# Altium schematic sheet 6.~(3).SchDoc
size 420 x 297 mm
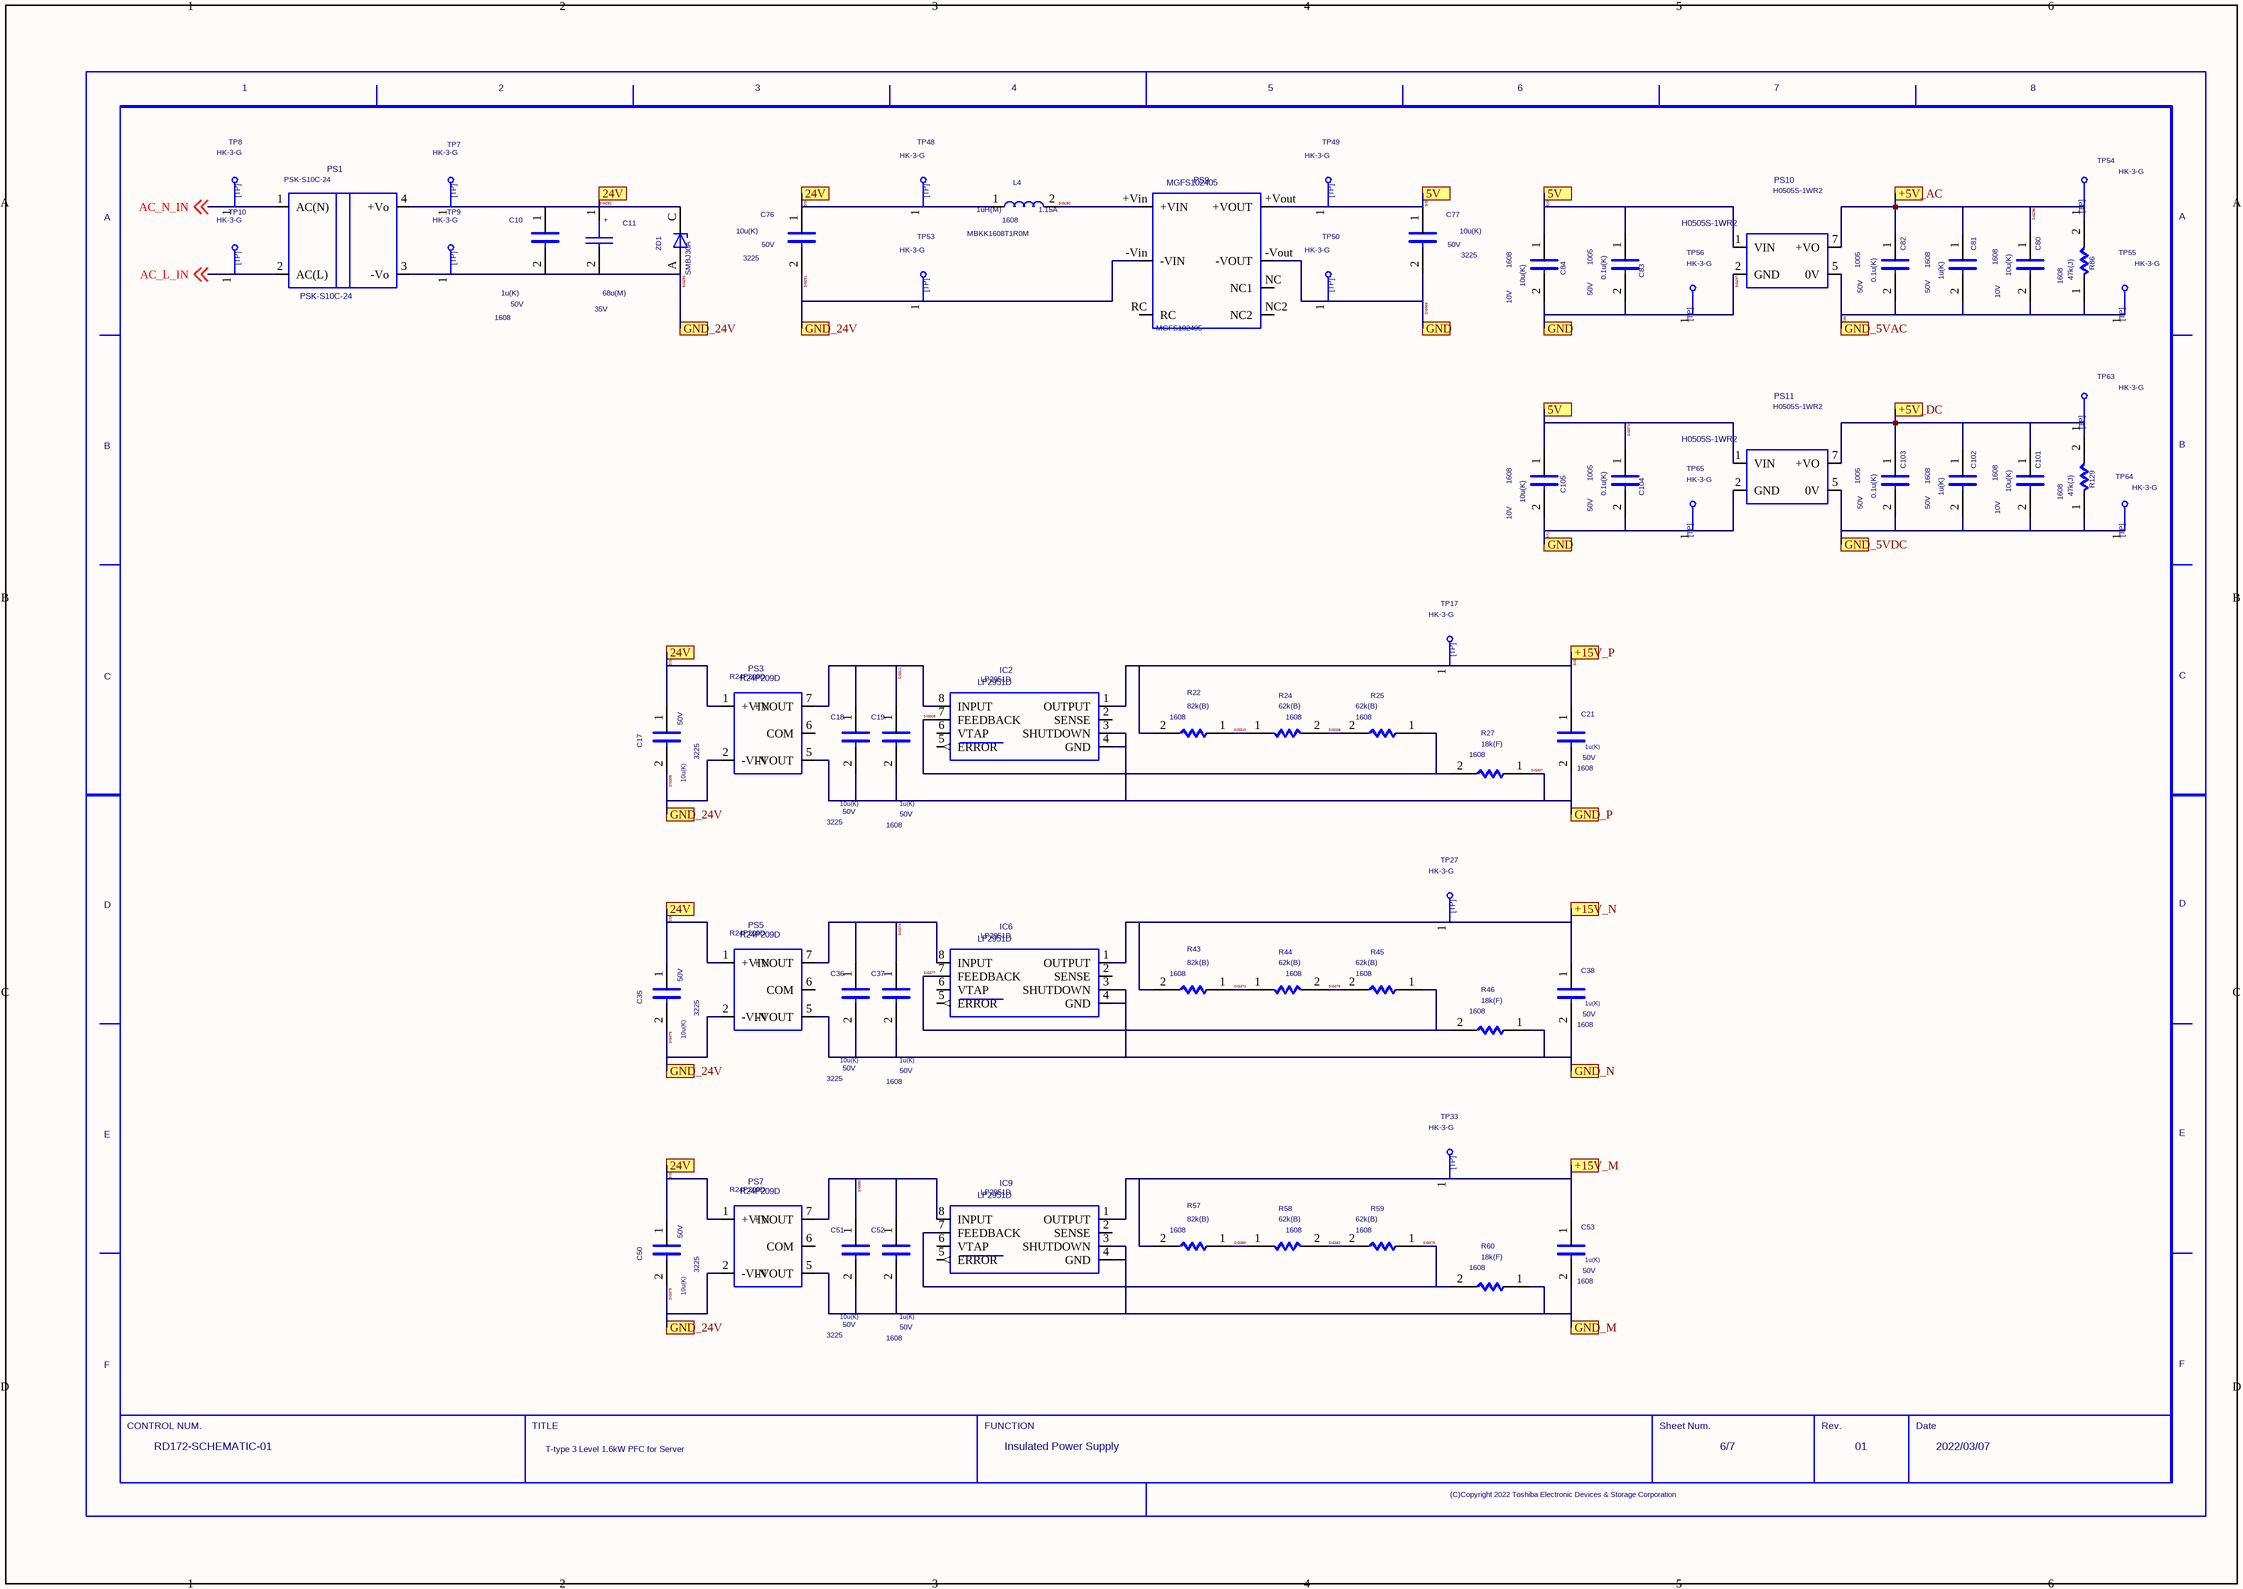
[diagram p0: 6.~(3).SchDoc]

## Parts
C10  SIZECODESMD: 1608  VAL2: 50V  VAL1: 1u(K)  (hidden comment: C)
C11  VAL2: 35V  VAL1: 68u(M)  (hidden comment: CP)
C17  SIZECODESMD: 3225  VAL2: 50V  VAL1: 10u(K)  (hidden comment: C)
C18  SIZECODESMD: 3225  VAL2: 50V  VAL1: 10u(K)  (hidden comment: C)
C19  SIZECODESMD: 1608  VAL2: 50V  VAL1: 1u(K)  (hidden comment: C)
C21  SIZECODESMD: 1608  VAL2: 50V  VAL1: 1u(K)  (hidden comment: C)
C35  SIZECODESMD: 3225  VAL2: 50V  VAL1: 10u(K)  (hidden comment: C)
C36  SIZECODESMD: 3225  VAL2: 50V  VAL1: 10u(K)  (hidden comment: C)
C37  SIZECODESMD: 1608  VAL2: 50V  VAL1: 1u(K)  (hidden comment: C)
C38  SIZECODESMD: 1608  VAL2: 50V  VAL1: 1u(K)  (hidden comment: C)
C50  SIZECODESMD: 3225  VAL2: 50V  VAL1: 10u(K)  (hidden comment: C)
C51  SIZECODESMD: 3225  VAL2: 50V  VAL1: 10u(K)  (hidden comment: C)
C52  SIZECODESMD: 1608  VAL2: 50V  VAL1: 1u(K)  (hidden comment: C)
C53  SIZECODESMD: 1608  VAL2: 50V  VAL1: 1u(K)  (hidden comment: C)
C76  SIZECODESMD: 3225  VAL2: 50V  VAL1: 10u(K)  (hidden comment: C)
C77  SIZECODESMD: 3225  VAL2: 50V  VAL1: 10u(K)  (hidden comment: C)
C80  SIZECODESMD: 1608  VAL2: 10V  VAL1: 10u(K)  (hidden comment: C)
C81  SIZECODESMD: 1608  VAL2: 50V  VAL1: 1u(K)  (hidden comment: C)
C82  SIZECODESMD: 1005  VAL2: 50V  VAL1: 0.1u(K)  (hidden comment: C)
C83  SIZECODESMD: 1005  VAL2: 50V  VAL1: 0.1u(K)  (hidden comment: C)
C84  SIZECODESMD: 1608  VAL2: 10V  VAL1: 10u(K)  (hidden comment: C)
C101  SIZECODESMD: 1608  VAL2: 10V  VAL1: 10u(K)  (hidden comment: C)
C102  SIZECODESMD: 1608  VAL2: 50V  VAL1: 1u(K)  (hidden comment: C)
C103  SIZECODESMD: 1005  VAL2: 50V  VAL1: 0.1u(K)  (hidden comment: C)
C104  SIZECODESMD: 1005  VAL2: 50V  VAL1: 0.1u(K)  (hidden comment: C)
C105  SIZECODESMD: 1608  VAL2: 10V  VAL1: 10u(K)  (hidden comment: C)
IC2  LP2951D
IC6  LP2951D
IC9  LP2951D
L4  VAL2: 1.15A  SIZECODESMD: 1608  VAL1: 1uH(M)  VAL3: MBKK1608T1R0M  (hidden comment: L)
PS1  PSK-S10C-24
PS3  R24P209D
PS5  R24P209D
PS7  R24P209D
PS9  MGFS102405
PS10  H0505S-1WR2
PS11  H0505S-1WR2
R22  SIZECODESMD: 1608  VAL1: 82k(B)  (hidden comment: R)
R24  SIZECODESMD: 1608  VAL1: 62k(B)  (hidden comment: R)
R25  SIZECODESMD: 1608  VAL1: 62k(B)  (hidden comment: R)
R27  SIZECODESMD: 1608  VAL1: 18k(F)  (hidden comment: R)
R43  SIZECODESMD: 1608  VAL1: 82k(B)  (hidden comment: R)
R44  SIZECODESMD: 1608  VAL1: 62k(B)  (hidden comment: R)
R45  SIZECODESMD: 1608  VAL1: 62k(B)  (hidden comment: R)
R46  SIZECODESMD: 1608  VAL1: 18k(F)  (hidden comment: R)
R57  SIZECODESMD: 1608  VAL1: 82k(B)  (hidden comment: R)
R58  SIZECODESMD: 1608  VAL1: 62k(B)  (hidden comment: R)
R59  SIZECODESMD: 1608  VAL1: 62k(B)  (hidden comment: R)
R60  SIZECODESMD: 1608  VAL1: 18k(F)  (hidden comment: R)
R86  SIZECODESMD: 1608  VAL1: 47k(J)  (hidden comment: R)
R129  SIZECODESMD: 1608  VAL1: 47k(J)  (hidden comment: R)
TP7  VAL3: HK-3-G  (hidden comment: TP)
TP8  VAL3: HK-3-G  (hidden comment: TP)
TP9  VAL3: HK-3-G  (hidden comment: TP)
TP10  VAL3: HK-3-G  (hidden comment: TP)
TP17  VAL3: HK-3-G  (hidden comment: TP)
TP27  VAL3: HK-3-G  (hidden comment: TP)
TP33  VAL3: HK-3-G  (hidden comment: TP)
TP48  VAL3: HK-3-G  (hidden comment: TP)
TP49  VAL3: HK-3-G  (hidden comment: TP)
TP50  VAL3: HK-3-G  (hidden comment: TP)
TP53  VAL3: HK-3-G  (hidden comment: TP)
TP54  VAL3: HK-3-G  (hidden comment: TP)
TP55  VAL3: HK-3-G  (hidden comment: TP)
TP56  VAL3: HK-3-G  (hidden comment: TP)
TP63  VAL3: HK-3-G  (hidden comment: TP)
TP64  VAL3: HK-3-G  (hidden comment: TP)
TP65  VAL3: HK-3-G  (hidden comment: TP)
U?  DATE: 2022/03/07  REVISION: 01  SHEETNUMBER: 6/7  TITLE: T-type 3 Level 1.6kW PFC for Server  DRAWINGNUMBER: RD172-SCHEMATIC-01  FUNCTION: Insulated Power Supply  (hidden comment: WAKU_DEF100)
ZD1  VAL3: SMBJ30A  (hidden comment: ZD)

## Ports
5V, 24V, +5V_AC, +5V_DC, +15V_M, +15V_N, +15V_P, GND, GND_5VAC, GND_5VDC, GND_24V, GND_M, GND_N, GND_P

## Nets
+5V_DC: C101.1 C102.1 C103.1 PS11.7(+VO) R129.2 TP63.1 ; port +5V_DC
+15V_M: C53.1 IC9.1(OUTPUT) R57.2 TP33.1 ; port +15V_M
+15V_N: C38.1 IC6.1(OUTPUT) R43.2 TP27.1 ; port +15V_N
AC_L_IN: PS1.2(AC(L)) TP10.1 ; off-sheet AC_L_IN
AC_N_IN: PS1.1(AC(N)) TP8.1 ; off-sheet AC_N_IN
GND_5VDC: C101.2 C102.2 C103.2 PS11.5(0V) R129.1 TP64.1 ; port GND_5VDC
GND_M: C51.2 C52.2 C53.2 IC9.3(SHUTDOWN) IC9.4(GND) PS7.5(-VOUT) R60.1 ; port GND_M
GND_N: C36.2 C37.2 C38.2 IC6.3(SHUTDOWN) IC6.4(GND) PS5.5(-VOUT) R46.1 ; port GND_N
SIG287: C77.1 C83.1 C84.1 C104.1 C105.1 PS9.+Vout(+VOUT) PS10.1(VIN) PS11.1(VIN) TP49.1 ; port 5V  [also labelled SIG298, SIG370]
SIG288: C10.1 C11.1 C17.1 C35.1 C50.1 C76.1 L4.1 PS1.4(+Vo) PS3.1(+VIN) PS5.1(+VIN) PS7.1(+VIN) TP7.1 TP48.1 ZD1.C ; port 24V  [also labelled SIG292, SIG304, SIG373, SIG381]
SIG290: L4.2 PS9.+Vin(+VIN)
SIG291: C10.2 C11.2 C17.2 C35.2 C50.2 C76.2 PS1.3(-Vo) PS3.2(-VIN) PS5.2(-VIN) PS7.2(-VIN) PS9.-Vin(-VIN) TP9.1 TP53.1 ZD1.A ; port GND_24V  [also labelled SIG293, SIG305, SIG375, SIG379]
SIG296: C80.1 C81.1 C82.1 PS10.7(+VO) R86.2 TP54.1 ; port +5V_AC
SIG297: C77.2 C83.2 C84.2 C104.2 C105.2 PS9.-Vout(-VOUT) PS10.2(GND) PS11.2(GND) TP50.1 TP56.1 TP65.1 ; port GND  [also labelled SIG369, SIG371]
SIG299: C80.2 C81.2 C82.2 PS10.5(0V) R86.1 TP55.1 ; port GND_5VAC
SIG306: C21.1 IC2.1(OUTPUT) R22.2 TP17.1 ; port +15V_P
SIG307: C18.2 C19.2 C21.2 IC2.3(SHUTDOWN) IC2.4(GND) PS3.5(-VOUT) R27.1 ; port GND_P
SIG308: R24.2 R25.2
SIG309: IC2.7(FEEDBACK) R25.1 R27.2
SIG310: R22.1 R24.1
SIG311: C18.1 C19.1 IC2.8(INPUT) PS3.7(+VOUT)
SIG372: R43.1 R44.1
SIG374: C36.1 C37.1 IC6.8(INPUT) PS5.7(+VOUT)
SIG376: R44.2 R45.2
SIG377: IC6.7(FEEDBACK) R45.1 R46.2
SIG378: IC9.7(FEEDBACK) R59.1 R60.2
SIG380: R57.1 R58.1
SIG382: R58.2 R59.2
SIG383: C51.1 C52.1 IC9.8(INPUT) PS7.7(+VOUT)

Not connected (* = marked no-connect by the designer): IC2 2(SENSE) 5(ERROR) 6(VTAP); IC6 2(SENSE) 5(ERROR) 6(VTAP); IC9 2(SENSE) 5(ERROR) 6(VTAP); PS3 6(COM); PS5 6(COM); PS7 6(COM); PS9 NC(NC1) NC2 RC

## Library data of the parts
C10 C19 C21 C37 C38 C52 C53 C81 C102 = C: OriginalSymbolOrigin: (2540,7620); COMP: -C-UMK107AB7105KA-T
C11 = CP: SAVEAREA0: -1450,-153,20294,13055; SAVECOUNT: 52; TIME: 15:02:55; UPDATEUSER: fukuda-y; UPDATETIME: 16:13:42; OriginalSymbolOrigin: (2540,10160); COMP: -C-EEHZC1V680XP
C17 C18 C35 C36 C50 C51 C76 C77 = C: OriginalSymbolOrigin: (2540,7620); COMP: -C-UMK325AB7106KM-T
C80 C84 C101 C105 = C: OriginalSymbolOrigin: (2540,7620); COMP: -C-GRM188D71A106KA73D
C82 C83 C103 C104 = C: OriginalSymbolOrigin: (2540,7620); COMP: -C-UMK105BJ104KV-F
IC2 IC6 IC9 = LP2951D: Voltage Regulators; MANUFACTURER: Txsas Instruments; COMP: -IC-LP2951D; TIME: 16:53:55; UPDATEUSER: t5459927; UPDATETIME: 16:15:29; SAVECOUNT: 3; SAVEAREA0: -15946,-25147,36340,13186; OriginalSymbolOrigin: (0,0)
L4 = L: OriginalSymbolOrigin: (2540,5080); COMP: -L-MBKK1608T1R0M
PS1 = PSK_S10C_24: AC/DC Converter; MANUFACTURER: CUI INC; COMP: -PS-PSK-S10C-24; TIME: 16:53:55; UPDATEUSER: t5459927; UPDATETIME: 14:43:43; SAVECOUNT: 2; SAVEAREA0: -3577,-18400,23236,1258; OriginalSymbolOrigin: (0,0)
PS3 PS5 PS7 = R24P209D: DC/DC Converter; MANUFACTURER: RECOM; COMP: -PS-R24P209D; TIME: 16:53:55; UPDATEUSER: t5459927; UPDATETIME: 16:11:38; SAVECOUNT: 2; SAVEAREA0: -5083,-15544,17282,852; OriginalSymbolOrigin: (0,0)
PS9 = MGFS102405: DC/DC Converter; MANUFACTURER: COSEL; COMP: -PS-MGFS102405_PIN; TIME: 16:53:55; UPDATEUSER: t5459927; UPDATETIME: 16:09:02; SAVECOUNT: 2; SAVEAREA0: -8909,-25908,28368,1421; OriginalSymbolOrigin: (0,0)
PS10 PS11 = H0505S_1WR2: DC/DC Converter; MANUFACTURER: MORNSUN; COMP: -PS-H0505S-1WR2; TIME: 16:53:55; UPDATEUSER: t5459927; UPDATETIME: 14:51:35; SAVECOUNT: 2; SAVEAREA0: -3365,-12675,18085,3050; OriginalSymbolOrigin: (0,0)
R22 R43 R57 = R: OriginalSymbolOrigin: (5080,5080); VAL2: 100mW; COMP: -R-ERA3ARB823V
R24 R25 R44 R45 R58 R59 = R: OriginalSymbolOrigin: (5080,5080); VAL2: 100mW; COMP: -R-ERA3APB623V
R27 R46 R60 = R: OriginalSymbolOrigin: (5080,5080); VAL2: 100mW; COMP: -R-RK73H1JTTD1802F
R86 R129 = R: OriginalSymbolOrigin: (5080,5080); COMP: -R-RK73B1JTTD473J; VAL2: 100mW
TP7-TP10 TP17 TP27 TP33 TP48-TP50 TP53-TP56 TP63-TP65 = TP: TIME: 16:12:21; UPDATEUSER: fukuda-y; UPDATETIME: 16:18:11; SAVECOUNT: 2; SAVEAREA0: -242,-92,12810,7836; OriginalSymbolOrigin: (0,7620); COMP: -TP-HK-3-G
U? = WAKU_DEF100: PLOTTIME: HH:MM; SAVEAREA0: -45080,-4508,463680,304612; TIME: 16:20:58; UPDATEUSER: t5459927; UPDATETIME: 09:34:25; SAVECOUNT: 7; OriginalSymbolOrigin: (10160,284480)
ZD1 = ZD: SAVEAREA0: -4630,-153,17114,13055; TIME: 14:49:55; UPDATEUSER: fukuda-y; UPDATETIME: 08:18:42; SAVECOUNT: 6; OriginalSymbolOrigin: (5080,5080); COMP: -D-SMBJ30A_AC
